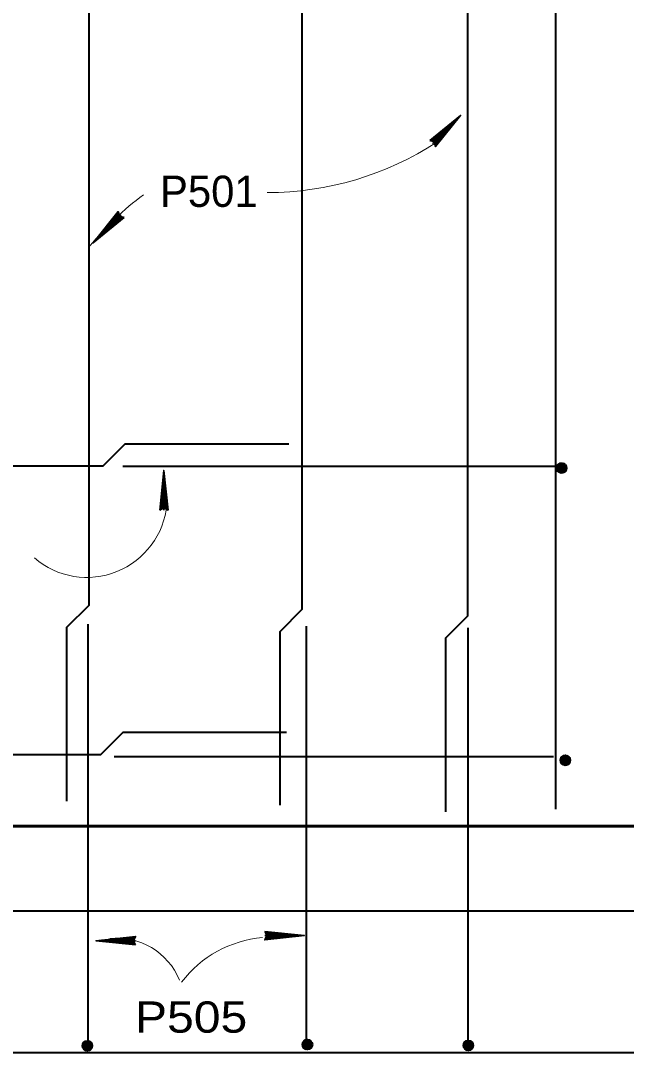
# Model space of a CAD drawing. Extents: x 14.14 to 17.34, y -1.61 to 0.38.
# Drawn here: x 14.9478 to 15.1093, y -1.2654 to -0.9903 of the extents above; entities that cross this region are included whole.
import ezdxf

# ---------------------------------------------------------------- set-up
doc = ezdxf.new("R2010")
doc.units = 0
doc.header["$LTSCALE"] = 0.0033
doc.layers.add('1', color=7, linetype='Continuous', lineweight=40)

msp = doc.modelspace()

# ---------------------------------------------------------------- linework, layer by layer
at = {"layer": '1'}
for p, q in [((15.090333, -0.89325), (15.090333, -1.200583)), ((14.975, -1.109083), (15.090583, -1.109083)), ((15.090833, -1.11025), (15.092833, -1.110583)), ((15.090917, -1.10975), (15.092917, -1.110167)), ((15.090917, -1.11), (15.092917, -1.110333)), ((15.090917, -1.110083), (15.092833, -1.110417)), ((15.090917, -1.110167), (15.092833, -1.1105)), ((15.091083, -1.108833), (15.091, -1.110333)), ((15.091, -1.109333), (15.093, -1.109667)), ((15.091, -1.109417), (15.093, -1.109833)), ((15.091, -1.1095), (15.092917, -1.109917)), ((15.091, -1.109583), (15.092917, -1.11)), ((15.091167, -1.108833), (15.091083, -1.110333)), ((15.091083, -1.108833), (15.093083, -1.109167)), ((15.091083, -1.108917), (15.093083, -1.10925)), ((15.091083, -1.109), (15.093083, -1.109417)), ((15.091083, -1.109083), (15.093083, -1.1095)), ((15.091083, -1.10925), (15.093, -1.109583)), ((15.091167, -1.108667), (15.093083, -1.109)), ((15.09125, -1.108833), (15.091167, -1.110333)), ((15.091333, -1.108833), (15.09125, -1.110333)), ((15.091417, -1.108833), (15.091333, -1.110333)), ((15.091583, -1.108833), (15.0915, -1.110333)), ((15.091667, -1.108833), (15.091583, -1.110333)), ((15.09175, -1.108833), (15.091667, -1.110333)), ((15.091833, -1.108833), (15.09175, -1.110333)), ((15.091917, -1.108833), (15.091833, -1.110333)), ((15.092, -1.108833), (15.091917, -1.110333)), ((15.092083, -1.108833), (15.092, -1.110333)), ((15.09225, -1.108917), (15.092083, -1.110417)), ((15.092417, -1.108917), (15.09225, -1.110417)), ((15.0925, -1.108917), (15.092417, -1.110417)), ((15.0925, -1.108917), (15.092417, -1.110417)), ((15.092583, -1.108917), (15.0925, -1.110417)), ((15.092667, -1.108917), (15.092583, -1.110417)), ((15.09275, -1.108917), (15.092667, -1.110417)), ((15.092833, -1.108917), (15.09275, -1.110417)), ((15.092917, -1.108917), (15.092833, -1.110417)), ((15.093, -1.108917), (15.092917, -1.110417)), ((15.093167, -1.108917), (15.093083, -1.110417)), ((14.965667, -1.15125), (14.965667, -1.26375)), ((15.023917, -1.15175), (15.023917, -1.264167)), ((15.067, -1.15225), (15.067, -1.264583)), ((14.972667, -1.1865), (15.089833, -1.1865)), ((15.091833, -1.188167), (15.093833, -1.1885)), ((15.091917, -1.187667), (15.093917, -1.188083)), ((15.091917, -1.187917), (15.093917, -1.18825)), ((15.091917, -1.188), (15.093833, -1.188333)), ((15.091917, -1.188083), (15.093833, -1.188417)), ((15.092083, -1.18675), (15.092, -1.18825)), ((15.092, -1.18725), (15.094, -1.187583)), ((15.092, -1.187333), (15.094, -1.18775)), ((15.092, -1.187417), (15.093917, -1.187833)), ((15.092, -1.1875), (15.093917, -1.187917)), ((15.092167, -1.18675), (15.092083, -1.18825)), ((15.092083, -1.18675), (15.094083, -1.187083)), ((15.092083, -1.186833), (15.094083, -1.187167)), ((15.092083, -1.186917), (15.094083, -1.187333)), ((15.092083, -1.187), (15.094083, -1.187417)), ((15.092083, -1.187167), (15.094, -1.1875)), ((15.092167, -1.186583), (15.094083, -1.186917)), ((15.09225, -1.18675), (15.092167, -1.18825)), ((15.092333, -1.18675), (15.09225, -1.18825)), ((15.092417, -1.18675), (15.092333, -1.18825)), ((15.092583, -1.18675), (15.0925, -1.18825)), ((15.092667, -1.18675), (15.092583, -1.18825)), ((15.09275, -1.18675), (15.092667, -1.18825)), ((15.092833, -1.18675), (15.09275, -1.18825)), ((15.092917, -1.18675), (15.092833, -1.18825)), ((15.093, -1.18675), (15.092917, -1.18825)), ((15.093083, -1.18675), (15.093, -1.18825)), ((15.09325, -1.186833), (15.093083, -1.188333)), ((15.093417, -1.186833), (15.09325, -1.188333)), ((15.0935, -1.186833), (15.093417, -1.188333)), ((15.0935, -1.186833), (15.093417, -1.188333)), ((15.093583, -1.186833), (15.0935, -1.188333)), ((15.093667, -1.186833), (15.093583, -1.188333)), ((15.09375, -1.186833), (15.093667, -1.188333)), ((15.093833, -1.186833), (15.09375, -1.188333)), ((15.093917, -1.186833), (15.093833, -1.188333)), ((15.094, -1.186833), (15.093917, -1.188333)), ((15.094167, -1.186833), (15.094083, -1.188333)), ((14.964917, -1.2625), (14.964583, -1.2645)), ((14.965, -1.262583), (14.964667, -1.2645)), ((14.965083, -1.262583), (14.96475, -1.2645)), ((14.965167, -1.262583), (14.964833, -1.264583)), ((14.965417, -1.262583), (14.965, -1.264583)), ((15.023583, -1.262167), (15.02325, -1.264167)), ((15.023667, -1.26225), (15.023333, -1.264167)), ((15.02375, -1.26225), (15.023417, -1.264167)), ((15.023833, -1.26225), (15.0235, -1.26425)), ((15.025, -1.262417), (15.0235, -1.262333)), ((15.025, -1.2625), (15.0235, -1.262417)), ((15.025, -1.262583), (15.0235, -1.2625)), ((15.025, -1.262667), (15.0235, -1.262583)), ((15.024083, -1.26225), (15.023667, -1.26425)), ((15.02425, -1.262333), (15.023833, -1.26425)), ((15.024333, -1.262333), (15.023917, -1.26425)), ((15.024417, -1.262333), (15.024, -1.264333)), ((15.0245, -1.262333), (15.024167, -1.264333)), ((15.024583, -1.262417), (15.02425, -1.264333)), ((15.02475, -1.262417), (15.024333, -1.264417)), ((15.024833, -1.262417), (15.024417, -1.264417)), ((15.024917, -1.262417), (15.024583, -1.264417)), ((15.025, -1.262417), (15.024667, -1.264417)), ((15.025167, -1.2625), (15.024833, -1.264417)), ((15.0665, -1.262417), (15.066167, -1.264417)), ((15.066583, -1.2625), (15.06625, -1.264417)), ((15.066667, -1.2625), (15.066333, -1.264417)), ((15.06675, -1.2625), (15.066417, -1.2645)), ((15.067917, -1.262667), (15.066417, -1.262583)), ((15.067, -1.2625), (15.066583, -1.2645)), ((15.067167, -1.262583), (15.06675, -1.2645)), ((15.06725, -1.262583), (15.066833, -1.2645)), ((15.067333, -1.262583), (15.066917, -1.264583)), ((15.067417, -1.262583), (15.067083, -1.264583)), ((14.96625, -1.263917), (14.96475, -1.26375)), ((14.96625, -1.264083), (14.96475, -1.263917)), ((14.96625, -1.264167), (14.96475, -1.264083)), ((14.96625, -1.264167), (14.96475, -1.264083)), ((14.96625, -1.26425), (14.96475, -1.264167)), ((14.96625, -1.264333), (14.96475, -1.26425)), ((14.96625, -1.264417), (14.96475, -1.264333)), ((14.96625, -1.2645), (14.96475, -1.264417)), ((14.96625, -1.264583), (14.96475, -1.2645)), ((14.96625, -1.264667), (14.96475, -1.264583)), ((14.96625, -1.264833), (14.96475, -1.26475)), ((14.966333, -1.26275), (14.964833, -1.262667)), ((14.966333, -1.262833), (14.964833, -1.26275)), ((14.966333, -1.262917), (14.964833, -1.262833)), ((14.966333, -1.263), (14.964833, -1.262917)), ((14.966333, -1.263083), (14.964833, -1.263)), ((14.966333, -1.26325), (14.964833, -1.263167)), ((14.966333, -1.263333), (14.964833, -1.26325)), ((14.966333, -1.263417), (14.964833, -1.263333)), ((14.966333, -1.2635), (14.964833, -1.263417)), ((14.966333, -1.263583), (14.964833, -1.2635)), ((14.966333, -1.263667), (14.964833, -1.263583)), ((14.966333, -1.26375), (14.964833, -1.263667)), ((14.965583, -1.262667), (14.965167, -1.264583)), ((14.965667, -1.262667), (14.96525, -1.264583)), ((14.96575, -1.262667), (14.965333, -1.264667)), ((14.965833, -1.262667), (14.9655, -1.264667)), ((14.965917, -1.26275), (14.965583, -1.264667)), ((14.966083, -1.26275), (14.965667, -1.26475)), ((14.966167, -1.26275), (14.96575, -1.26475)), ((14.96625, -1.26275), (14.965917, -1.26475)), ((14.966333, -1.26275), (14.966, -1.26475)), ((14.9665, -1.262833), (14.966167, -1.26475)), ((15.024917, -1.263583), (15.023417, -1.263417)), ((15.024917, -1.26375), (15.023417, -1.263583)), ((15.024917, -1.263833), (15.023417, -1.26375)), ((15.024917, -1.263833), (15.023417, -1.26375)), ((15.024917, -1.263917), (15.023417, -1.263833)), ((15.024917, -1.264), (15.023417, -1.263917)), ((15.024917, -1.264083), (15.023417, -1.264)), ((15.024917, -1.264167), (15.023417, -1.264083)), ((15.024917, -1.26425), (15.023417, -1.264167)), ((15.024917, -1.264333), (15.023417, -1.26425)), ((15.024917, -1.2645), (15.023417, -1.264417)), ((15.025, -1.26275), (15.0235, -1.262667)), ((15.025, -1.262917), (15.0235, -1.262833)), ((15.025, -1.263), (15.0235, -1.262917)), ((15.025, -1.263083), (15.0235, -1.263)), ((15.025, -1.263167), (15.0235, -1.263083)), ((15.025, -1.26325), (15.0235, -1.263167)), ((15.025, -1.263333), (15.0235, -1.26325)), ((15.025, -1.263417), (15.0235, -1.263333)), ((15.067833, -1.263833), (15.066333, -1.263667)), ((15.067833, -1.264), (15.066333, -1.263833)), ((15.067833, -1.264083), (15.066333, -1.264)), ((15.067833, -1.264083), (15.066333, -1.264)), ((15.067833, -1.264167), (15.066333, -1.264083)), ((15.067833, -1.26425), (15.066333, -1.264167)), ((15.067833, -1.264333), (15.066333, -1.26425)), ((15.067833, -1.264417), (15.066333, -1.264333)), ((15.067833, -1.2645), (15.066333, -1.264417)), ((15.067833, -1.264583), (15.066333, -1.2645)), ((15.067833, -1.26475), (15.066333, -1.264667)), ((15.067917, -1.26275), (15.066417, -1.262667)), ((15.067917, -1.262833), (15.066417, -1.26275)), ((15.067917, -1.262917), (15.066417, -1.262833)), ((15.067917, -1.263), (15.066417, -1.262917)), ((15.067917, -1.263167), (15.066417, -1.263083)), ((15.067917, -1.26325), (15.066417, -1.263167)), ((15.067917, -1.263333), (15.066417, -1.26325)), ((15.067917, -1.263417), (15.066417, -1.263333)), ((15.067917, -1.2635), (15.066417, -1.263417)), ((15.067917, -1.263583), (15.066417, -1.2635)), ((15.067917, -1.263667), (15.066417, -1.263583)), ((15.0675, -1.262667), (15.067167, -1.264583)), ((15.067667, -1.262667), (15.06725, -1.264667)), ((15.06775, -1.262667), (15.067333, -1.264667)), ((15.067833, -1.262667), (15.0675, -1.264667)), ((15.067917, -1.262667), (15.067583, -1.264667)), ((15.068083, -1.26275), (15.06775, -1.264667))]:
    msp.add_line(p, q, dxfattribs=at)
at = {"layer": '1', "lineweight": 35}
for p, q in [((15.057, -1.022167), (15.06325, -1.017333)), ((15.057, -1.022167), (15.06325, -1.017333)), ((15.057083, -1.02225), (15.06325, -1.017333)), ((15.057167, -1.022333), (15.06325, -1.017333)), ((15.057167, -1.022333), (15.063417, -1.0175)), ((15.057583, -1.023083), (15.065083, -1.015583)), ((15.058167, -1.023417), (15.062833, -1.01775)), ((15.058333, -1.0235), (15.062917, -1.01775)), ((15.058417, -1.023583), (15.063083, -1.017833)), ((15.0585, -1.023667), (15.063083, -1.017917)), ((14.974583, -1.042083), (14.967083, -1.049583)), ((14.973583, -1.0415), (14.969, -1.04725)), ((14.97375, -1.041667), (14.969083, -1.047333)), ((14.973833, -1.041667), (14.969167, -1.0475)), ((14.974, -1.04175), (14.969333, -1.0475)), ((14.975, -1.042833), (14.96875, -1.047667)), ((14.975, -1.042833), (14.968833, -1.047833)), ((14.975, -1.042917), (14.968917, -1.047917)), ((14.975083, -1.043), (14.968917, -1.047917)), ((14.975083, -1.043), (14.968917, -1.047917)), ((14.985917, -1.120833), (14.985917, -1.11025)), ((14.984917, -1.120583), (14.985833, -1.11275)), ((14.984917, -1.120583), (14.985833, -1.11275)), ((14.985, -1.120583), (14.985833, -1.11275)), ((14.985083, -1.120583), (14.985917, -1.11275)), ((14.985083, -1.120583), (14.986083, -1.11275)), ((14.986583, -1.120667), (14.985833, -1.113333)), ((14.98675, -1.120583), (14.985917, -1.11325)), ((14.986833, -1.120583), (14.986083, -1.11325)), ((14.987, -1.120583), (14.986167, -1.11325)), ((14.978167, -1.234583), (14.970833, -1.235417)), ((14.978167, -1.23475), (14.970833, -1.2355)), ((14.978167, -1.234833), (14.970833, -1.235667)), ((14.97825, -1.235), (14.970917, -1.23575)), ((15.012833, -1.23425), (15.023417, -1.23425)), ((15.013, -1.234917), (15.020333, -1.234167)), ((15.013083, -1.23325), (15.020917, -1.234167)), ((15.013083, -1.23325), (15.020917, -1.234167)), ((15.013083, -1.233333), (15.020917, -1.234167)), ((15.013083, -1.233417), (15.020917, -1.23425)), ((15.013083, -1.233417), (15.020917, -1.234417)), ((15.013083, -1.235083), (15.020417, -1.23425)), ((15.013083, -1.235167), (15.020417, -1.234417)), ((15.013083, -1.235333), (15.020417, -1.2345)), ((14.978417, -1.235667), (14.967833, -1.235667)), ((14.978167, -1.2365), (14.970333, -1.2355)), ((14.978167, -1.2365), (14.970333, -1.235667)), ((14.978167, -1.236667), (14.970333, -1.23575)), ((14.978167, -1.236667), (14.970333, -1.23575)), ((14.978167, -1.236583), (14.970333, -1.23575))]:
    msp.add_line(p, q, dxfattribs=at)
at = {"layer": '1'}
for points in [[(14.96, -0.89375), (14.96, -0.932), (14.965917, -0.937917), (14.965917, -1.14625), (14.96, -1.152167), (14.96, -1.198417)], [(15.016833, -0.893167), (15.016833, -0.933083), (15.02275, -0.939), (15.02275, -1.147333), (15.016833, -1.15325), (15.016833, -1.1995)], [(15.066917, -0.89275), (15.066917, -1.149083), (15.061, -1.155), (15.061, -1.20125)], [(15.01925, -1.10325), (14.975583, -1.10325), (14.969667, -1.109167), (14.754917, -1.109167), (14.66, -1.109167), (14.654083, -1.10325), (14.61075, -1.10325)], [(15.090667, -1.109667), (15.09325, -1.109333), (15.090917, -1.108833), (15.09325, -1.109917), (15.090833, -1.110333), (15.092833, -1.110667), (15.092833, -1.108583), (15.091917, -1.110917), (15.092167, -1.108333), (15.091167, -1.110667), (15.0915, -1.108333), (15.092333, -1.110917), (15.09075, -1.109167), (15.093167, -1.109), (15.0915, -1.110833), (15.092583, -1.108417), (15.090917, -1.108833), (15.090833, -1.110333), (15.091917, -1.110917), (15.092833, -1.110667), (15.09325, -1.109917), (15.093167, -1.109), (15.092583, -1.108417), (15.091917, -1.1095), (15.093083, -1.110417), (15.091167, -1.110667), (15.091917, -1.1095), (15.090833, -1.109), (15.091833, -1.108333), (15.091917, -1.109417), (15.09275, -1.110667), (15.09075, -1.109417), (15.092083, -1.109083), (15.092833, -1.108583)], [(15.018667, -1.180167), (14.975, -1.180167), (14.969083, -1.186083), (14.754333, -1.186083), (14.659417, -1.186083), (14.6535, -1.180167), (14.610167, -1.180167)], [(15.091667, -1.187583), (15.09425, -1.18725), (15.091917, -1.18675), (15.09425, -1.187833), (15.091833, -1.18825), (15.093833, -1.188583), (15.093833, -1.1865), (15.092917, -1.188833), (15.093167, -1.18625), (15.092167, -1.188583), (15.0925, -1.18625), (15.093333, -1.188833), (15.09175, -1.187083), (15.094167, -1.186917), (15.0925, -1.18875), (15.093583, -1.186333), (15.091917, -1.18675), (15.091833, -1.18825), (15.092917, -1.188833), (15.093833, -1.188583), (15.09425, -1.187833), (15.094167, -1.186917), (15.093583, -1.186333), (15.092917, -1.187417), (15.094083, -1.188333), (15.092167, -1.188583), (15.092917, -1.187417), (15.091833, -1.186917), (15.092833, -1.18625), (15.092917, -1.187333), (15.09375, -1.188583), (15.09175, -1.187333), (15.093083, -1.187), (15.093833, -1.1865)], [(14.772417, -1.2235), (14.83475, -1.2235), (14.842, -1.227667), (15.177417, -1.227667)], [(14.7725, -1.26125), (14.834083, -1.26125), (14.841333, -1.265417), (15.17825, -1.265417)], [(14.9655, -1.262333), (14.965833, -1.264917), (14.966333, -1.262583), (14.96525, -1.264917), (14.964833, -1.2625), (14.9645, -1.2645), (14.966583, -1.2645), (14.96425, -1.263583), (14.966833, -1.263833), (14.9645, -1.262833), (14.966833, -1.263167), (14.96425, -1.264), (14.966, -1.262417), (14.966167, -1.264833), (14.964333, -1.263167), (14.96675, -1.26425), (14.966333, -1.262583), (14.964833, -1.2625), (14.96425, -1.263583), (14.9645, -1.2645), (14.96525, -1.264917), (14.966167, -1.264833), (14.96675, -1.26425), (14.965667, -1.263583), (14.96475, -1.26475), (14.9645, -1.262833), (14.965667, -1.263583), (14.966167, -1.2625), (14.966833, -1.2635), (14.96575, -1.263583), (14.9645, -1.264417), (14.96575, -1.262417), (14.966083, -1.26375), (14.966583, -1.2645)], [(15.024167, -1.262), (15.0245, -1.264583), (15.025, -1.26225), (15.023917, -1.264583), (15.0235, -1.262167), (15.023167, -1.264167), (15.02525, -1.264167), (15.022917, -1.26325), (15.0255, -1.2635), (15.023167, -1.2625), (15.0255, -1.262833), (15.022917, -1.263667), (15.024667, -1.262083), (15.024833, -1.2645), (15.023, -1.262833), (15.025417, -1.263917), (15.025, -1.26225), (15.0235, -1.262167), (15.022917, -1.26325), (15.023167, -1.264167), (15.023917, -1.264583), (15.024833, -1.2645), (15.025417, -1.263917), (15.024333, -1.26325), (15.023417, -1.264417), (15.023167, -1.2625), (15.024333, -1.26325), (15.024833, -1.262167), (15.0255, -1.263167), (15.024417, -1.26325), (15.023167, -1.264083), (15.024417, -1.262083), (15.02475, -1.263417), (15.02525, -1.264167)], [(15.067083, -1.26225), (15.067417, -1.264833), (15.067917, -1.2625), (15.066833, -1.264833), (15.066417, -1.262417), (15.066083, -1.264417), (15.068167, -1.264417), (15.065833, -1.2635), (15.068417, -1.26375), (15.066083, -1.26275), (15.068417, -1.263083), (15.065833, -1.263917), (15.067583, -1.262333), (15.06775, -1.26475), (15.065917, -1.263083), (15.068333, -1.264167), (15.067917, -1.2625), (15.066417, -1.262417), (15.065833, -1.2635), (15.066083, -1.264417), (15.066833, -1.264833), (15.06775, -1.26475), (15.068333, -1.264167), (15.06725, -1.2635), (15.066333, -1.264667), (15.066083, -1.26275), (15.06725, -1.2635), (15.06775, -1.262417), (15.068417, -1.263417), (15.067333, -1.2635), (15.066083, -1.264333), (15.067333, -1.262333), (15.067667, -1.263667), (15.068167, -1.264417)]]:
    msp.add_lwpolyline(points, dxfattribs=at)
at = {"layer": '1', "lineweight": 35}
for points in [[(15.056833, -1.022333), (15.065083, -1.015583), (15.058417, -1.023917), (15.058, -1.022667)], [(15.058, -1.0225), (15.06125, -1.019083), (15.061333, -1.019167), (15.060667, -1.019833), (15.058, -1.022417), (15.06, -1.02025), (15.05775, -1.022417), (15.05925, -1.02075), (15.057583, -1.022333), (15.06025, -1.02), (15.063667, -1.016833), (15.06325, -1.017667), (15.064083, -1.01675), (15.05825, -1.022667), (15.06, -1.021083), (15.05825, -1.022917), (15.061667, -1.018833), (15.058417, -1.023083)], [(14.975333, -1.042833), (14.967083, -1.049583), (14.97375, -1.04125), (14.974167, -1.0425)], [(14.974083, -1.042667), (14.970833, -1.046083), (14.97075, -1.046), (14.971417, -1.045333), (14.974167, -1.04275), (14.972083, -1.044917), (14.974417, -1.04275), (14.972833, -1.044417), (14.9745, -1.042833), (14.971833, -1.045167), (14.968417, -1.048333), (14.968917, -1.0475), (14.968, -1.048417), (14.973917, -1.0425), (14.972083, -1.044083), (14.973917, -1.04225), (14.970417, -1.046333), (14.97375, -1.042083)], [(14.984833, -1.120833), (14.985917, -1.11025), (14.987083, -1.120833), (14.985917, -1.12025)], [(14.985833, -1.120083), (14.98575, -1.115417), (14.985833, -1.115417), (14.985833, -1.116333), (14.98575, -1.120083), (14.985667, -1.117083), (14.985583, -1.12025), (14.9855, -1.118), (14.985417, -1.12025), (14.985667, -1.11675), (14.985833, -1.112083), (14.986083, -1.113), (14.986083, -1.11175), (14.986083, -1.120083), (14.98625, -1.117667), (14.98625, -1.12025), (14.985833, -1.114917), (14.9865, -1.12025)], [(14.978417, -1.23675), (14.967833, -1.235667), (14.978417, -1.2345), (14.977833, -1.235667)], [(14.977667, -1.23575), (14.973, -1.235833), (14.973, -1.23575), (14.973917, -1.23575), (14.977667, -1.235833), (14.974667, -1.235917), (14.977833, -1.236), (14.975583, -1.236083), (14.977833, -1.236167), (14.974333, -1.235917), (14.969667, -1.23575), (14.970583, -1.2355), (14.969333, -1.2355), (14.977667, -1.2355), (14.97525, -1.235333), (14.977833, -1.235333), (14.9725, -1.23575), (14.977833, -1.235083)], [(15.012833, -1.233167), (15.023417, -1.23425), (15.012833, -1.235417), (15.013417, -1.23425)], [(15.013583, -1.234167), (15.01825, -1.234083), (15.01825, -1.234167), (15.017333, -1.234167), (15.013583, -1.234083), (15.016583, -1.234), (15.013417, -1.233917), (15.015667, -1.233833), (15.013417, -1.23375), (15.016917, -1.234), (15.021583, -1.234167), (15.020667, -1.234417), (15.021917, -1.234417), (15.013583, -1.234417), (15.016, -1.234583), (15.013417, -1.234583), (15.01875, -1.234167), (15.013417, -1.234833)]]:
    msp.add_lwpolyline(points, close=True, dxfattribs=at)
for points in [[(15.058, -1.0225), (15.05725, -1.02225), (15.057583, -1.02225), (15.057917, -1.022333), (15.058, -1.022167), (15.057667, -1.022), (15.058083, -1.022667), (15.058333, -1.023167), (15.058417, -1.023583)], [(14.974083, -1.042667), (14.974917, -1.042917), (14.974583, -1.042917), (14.97425, -1.042833), (14.974083, -1.043083), (14.974417, -1.043167), (14.974, -1.0425), (14.973833, -1.042083), (14.973667, -1.041583)], [(14.985833, -1.120083), (14.985083, -1.1205), (14.985333, -1.12025), (14.985667, -1.120083), (14.985583, -1.119833), (14.98525, -1.12), (14.986, -1.120167), (14.9865, -1.120333), (14.986917, -1.120583)], [(14.977667, -1.23575), (14.978083, -1.2365), (14.977833, -1.23625), (14.977667, -1.235917), (14.977417, -1.236), (14.977583, -1.236333), (14.97775, -1.235583), (14.977917, -1.235083), (14.978167, -1.234667)], [(15.013583, -1.234167), (15.013167, -1.233417), (15.013417, -1.233667), (15.013583, -1.234), (15.013833, -1.233917), (15.013667, -1.233583), (15.0135, -1.234333), (15.013333, -1.234833), (15.013083, -1.23525)]]:
    msp.add_lwpolyline(points, dxfattribs=at)
at = {"layer": '1', "lineweight": 60}
msp.add_lwpolyline([(14.52925, -1.205083), (14.772417, -1.205083), (15.112583, -1.205083)], dxfattribs=at)
at = {"layer": '1'}
for centre in [(15.092, -1.109617), (15.093, -1.187533), (14.96555, -1.263667), (15.024217, -1.263333), (15.067133, -1.263583)]:
    msp.add_circle(centre, 0.00132, dxfattribs=at)
at = {"layer": '1', "lineweight": 13}
for centre, radius, start, end in [((15.013585, -0.953674), 0.082492, 269.94116, 303.17307), ((15.0278, -1.100332), 0.079246, 126.64665, 140.95925), ((14.965416, -1.117364), 0.021425, 229.20279, 354.72583), ((14.973548, -1.252771), 0.017806, 21.77133, 96.60391), ((15.014812, -1.265107), 0.030382, 94.83783, 142.63079)]:
    msp.add_arc(centre, radius, start, end, dxfattribs=at)

# ---------------------------------------------------------------- texts
at = {"layer": '1'}
msp.add_text('P501', height=0.008334, dxfattribs=at).set_placement((14.984917, -1.04))
at = {"layer": '1', "width": 1.15}
msp.add_text('P505', height=0.008334, dxfattribs=at).set_placement((14.97825, -1.260167))

doc.saveas('drawing.dxf')
